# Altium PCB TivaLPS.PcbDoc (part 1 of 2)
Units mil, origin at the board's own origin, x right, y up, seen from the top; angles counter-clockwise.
Board outline 2370 x 2970 mil, 2 copper layers (TopLayer, BottomLayer), stack 30.45 mil thick; 141 components, 125 nets, 734 pads, 136 vias.
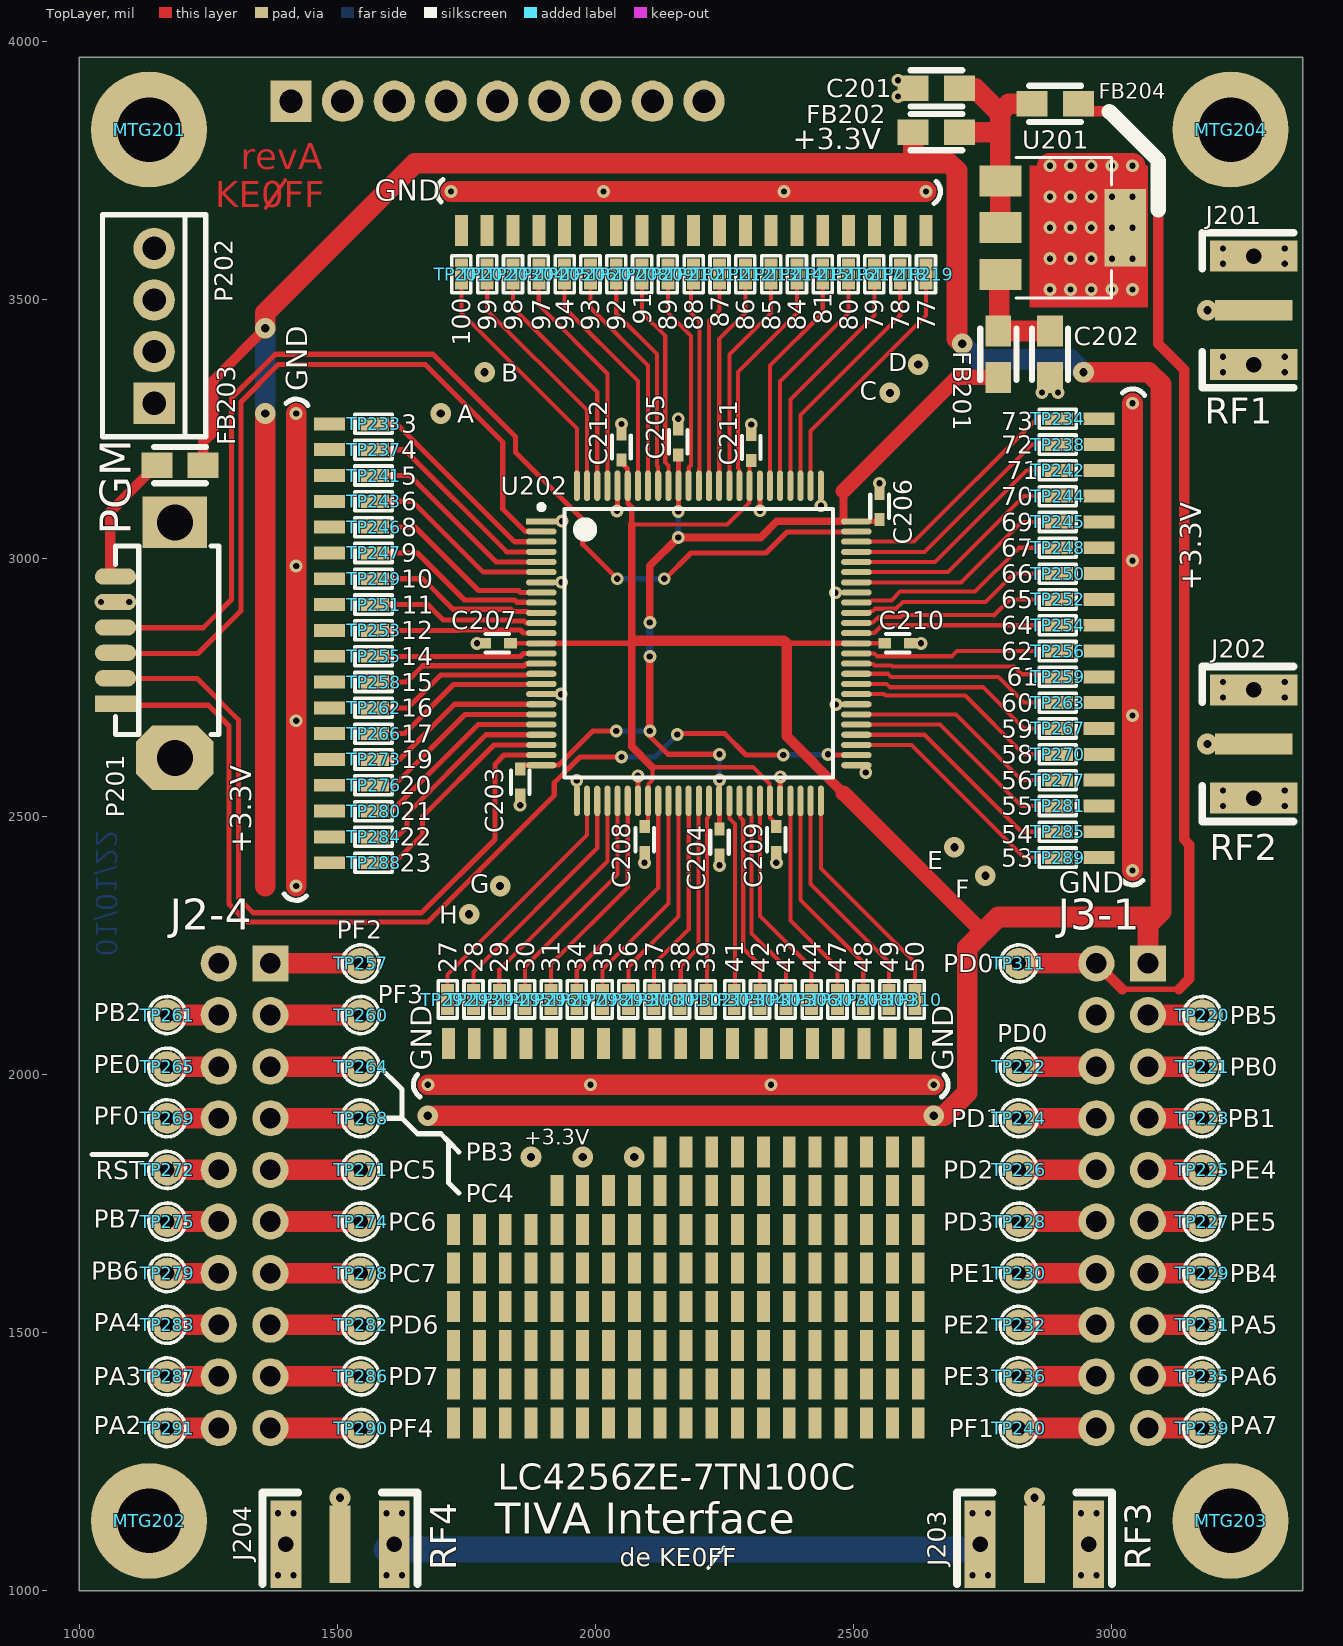
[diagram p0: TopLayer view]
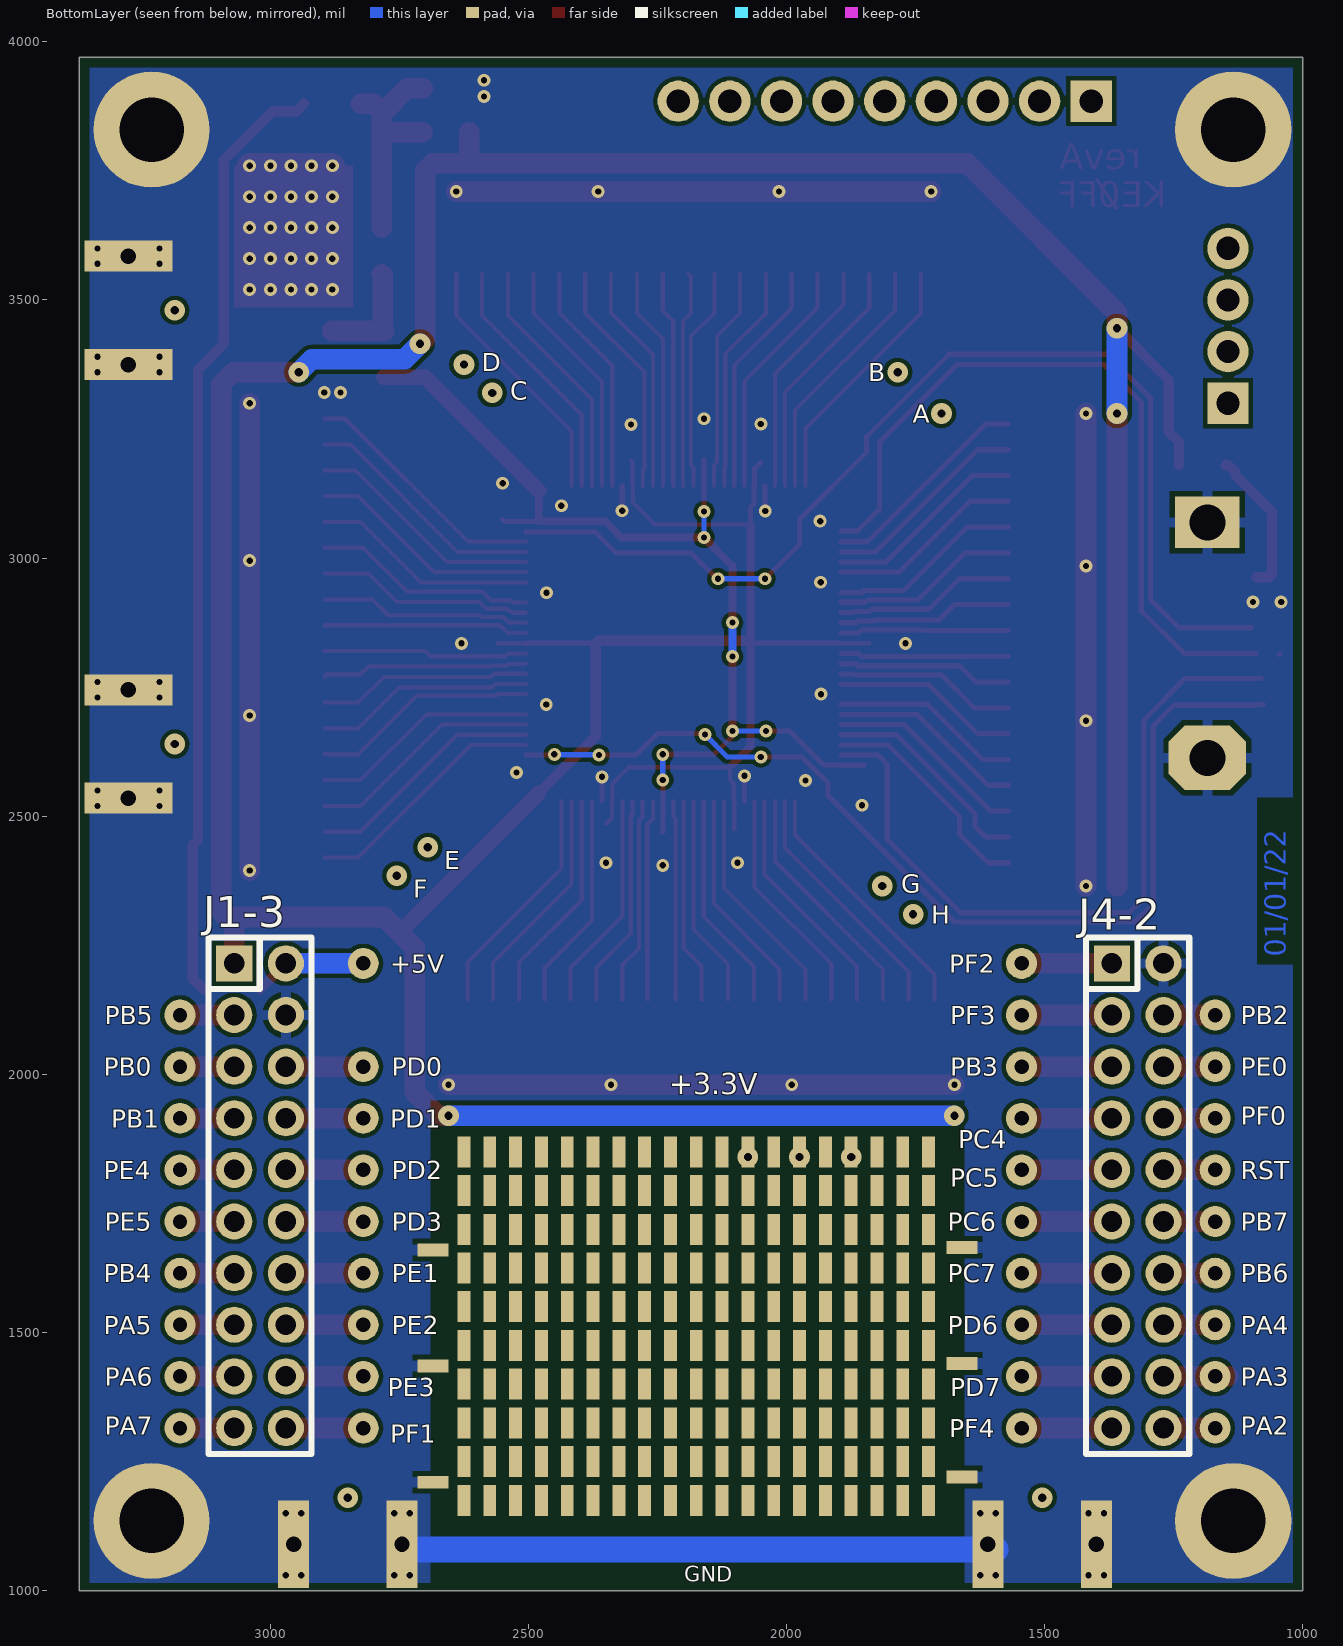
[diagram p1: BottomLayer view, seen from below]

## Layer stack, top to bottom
TopSolder: solder mask 0.4, Solder Resist, Dk 3.5
TopLayer: signal copper 1.4
Dielectric1: dielectric 27.65, FR-4, Dk 4.8
BottomLayer: signal copper 1.4
BottomSolder: solder mask 0.4, Solder Resist, Dk 3.5

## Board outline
1000,1000 3370,1000 3370,3970 1000,3970

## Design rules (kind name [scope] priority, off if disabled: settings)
Clearance Clearance_11 [Component=U202] p1: gap=6 ignorepadtopadclearanceinfootprint=FALSE
Clearance Clearance_8 [HasFootprint('QFP50P900X900X120-49N')] p2: gap=6 ignorepadtopadclearanceinfootprint=FALSE
Clearance Clearance_7 [InNet('FIL_CLK') vs InNet('GND')] p3: gap=6 ignorepadtopadclearanceinfootprint=FALSE
Clearance Clearance_6 [InNet('USB0D_N') vs InNet('USB0D_P')] p4: gap=6 ignorepadtopadclearanceinfootprint=FALSE
Clearance Clearance_10 [InNet('USB1D_N') vs InNet('USB1D_P')] p5: gap=6 ignorepadtopadclearanceinfootprint=FALSE
Clearance Clearance_9 [InNet('USBU_N') vs InNet('USBU_P')] p6: gap=6 ignorepadtopadclearanceinfootprint=FALSE
Clearance Clearance_4 [HasFootprint('0805') vs InNet('GND2')] p7: gap=25 ignorepadtopadclearanceinfootprint=FALSE
Clearance Clearance_3 [InNet('GND2')] p8: gap=8 ignorepadtopadclearanceinfootprint=FALSE
Clearance Clearance_2 [HasFootprint('MT1818')] p9: gap=6 ignorepadtopadclearanceinfootprint=FALSE
Clearance Clearance_1 [HasFootprint('32LFCSP_VQ')] p10: gap=5.7 ignorepadtopadclearanceinfootprint=FALSE
Clearance Clearance_5 [HasFootprint('CON_USB-MICRO')] p11: gap=5.7 ignorepadtopadclearanceinfootprint=FALSE
Clearance [All] p12: gap=8 ignorepadtopadclearanceinfootprint=FALSE
ComponentClearance ComponentClearance_2 [InComponent('TP8') vs InComponent('P2')] p1: gap=0 collisioncheckmode=3 verticalgap=10 showdistances=FALSE
ComponentClearance ComponentClearance_1 [InComponent('C34') vs InComponent('P2')] p2: gap=0 collisioncheckmode=3 verticalgap=10 showdistances=FALSE
ComponentClearance ComponentClearance_6 [InComponent('TP14') vs InComponent('C37')] p3: gap=0 collisioncheckmode=3 verticalgap=10 showdistances=FALSE
ComponentClearance ComponentClearance_9 [InComponent('L3')] p4: gap=0 collisioncheckmode=3 verticalgap=10 showdistances=FALSE
ComponentClearance ComponentClearance_3 [InComponent('D2')] p5: gap=0 collisioncheckmode=3 verticalgap=10 showdistances=FALSE
ComponentClearance ComponentClearance_5 [HasFootprint('0603')] p6: gap=0 collisioncheckmode=3 verticalgap=10 showdistances=FALSE
ComponentClearance ComponentClearance_8 [HasFootprint('TQFP-64')] p7: gap=0 collisioncheckmode=3 verticalgap=10 showdistances=FALSE
ComponentClearance ComponentClearance_10 [HasFootprint('USB_MICRO_SMD')] p8: gap=0 collisioncheckmode=3 verticalgap=10 showdistances=FALSE
ComponentClearance ComponentClearance_7 [HasFootprint('DF782')] p9: gap=0 collisioncheckmode=3 verticalgap=10 showdistances=FALSE
ComponentClearance ComponentClearance_4 [HasFootprint('0402')] p10: gap=0 collisioncheckmode=3 verticalgap=10 showdistances=FALSE
ComponentClearance [All] p11: gap=6 collisioncheckmode=3 verticalgap=10 showdistances=FALSE
DiffPairsRouting [All] p1: maxlimit=10 minlimit=6 mostfreqgap=6 toplayer_minwidth=10 toplayer_maxwidth=30 toplayer_prefwidth=28 bottomlayer_minwidth=10 bottomlayer_maxwidth=30 bottomlayer_prefwidth=28 maxuncoupledlength=500
FabricationTestPointUsage TestPointUsage [All] p1: valid=0 allowmultiple=FALSE
FabricationTestpoint Testpoint [All] p1: side=3 testpointundercomponent=TRUE minsize=40 maxsize=100 preferedsize=60 minholesize=20 maxholesize=40 preferedholesize=32 testpointgrid=1 allowsidetop=TRUE allowsidebottom=TRUE usegrid=TRUE gridtolerance=0.01
HoleSize [All] p1: absolutevalues=TRUE maxlimit=200 minlimit=1 maxpercent=80.000 minpercent=20.000
MinimumAnnularRing [All] p1: minimumring=6
MinimumSolderMaskSliver [All] p1: minsoldermaskwidth=6
PolygonConnect PolygonConnect_1 [(HoleSize    = 12.00) And (ViaDiameter = 25.00)] p1: connectstyle=Direct reliefconductorwidth=10 reliefentries=4 polygonreliefangle="90 Angle" airgapwidth=10
PolygonConnect PolygonConnect_8 [(PadXSize_BottomLayer = 25.00) And (PadYSize_BottomLayer = 20.00)] p2: connectstyle=Relief reliefconductorwidth=10 reliefentries=4 polygonreliefangle="90 Angle" airgapwidth=10
PolygonConnect PolygonConnect_7 [(PadXSize_BottomLayer = 20.00) And (PadYSize_BottomLayer = 25.00)] p3: connectstyle=Relief reliefconductorwidth=10 reliefentries=4 polygonreliefangle="90 Angle" airgapwidth=10
PolygonConnect PolygonConnect_5 [(PadXSize_TopLayer = 60.00) And (PadYSize_TopLayer = 170.00)] p4: connectstyle=Relief reliefconductorwidth=15 reliefentries=4 polygonreliefangle="90 Angle" airgapwidth=10
PolygonConnect PolygonConnect_6 [(PadXSize_TopLayer = 225.00) And (PadYSize_TopLayer = 225.00)] p5: connectstyle=Direct reliefconductorwidth=10 reliefentries=4 polygonreliefangle="90 Angle" airgapwidth=10
PolygonConnect PolygonConnect_4 [(PadXSize_TopLayer = 170.00) And (PadYSize_TopLayer = 60.00)] p6: connectstyle=Direct reliefconductorwidth=10 reliefentries=4 polygonreliefangle="90 Angle" airgapwidth=10
PolygonConnect PolygonConnect_3 [(PadXSize_TopLayer = 200.00) And (PadYSize_TopLayer = 200.00)] p7: connectstyle=Direct reliefconductorwidth=10 reliefentries=4 polygonreliefangle="90 Angle" airgapwidth=10
PolygonConnect PolygonConnect_2 [(PadXSize_TopLayer = 75.00) And (PadYSize_TopLayer = 115.00)] p8: connectstyle=Direct reliefconductorwidth=10 reliefentries=4 polygonreliefangle="90 Angle" airgapwidth=10
PolygonConnect [All] p9: connectstyle=Relief reliefconductorwidth=20 reliefentries=4 polygonreliefangle="90 Angle" airgapwidth=10
RoomDefinition MachShield [InComponentClass('MachShield')] p1: confinementstyle=ConfineOut formatcopy=TRUE lockcomponents=FALSE outline 55,55 730,55 730,190 55,190
RoutingVias [All] p1: holewidth=12 width=25 viastyle="Through Hole" minholewidth=12 minwidth=25 maxholewidth=125 maxwidth=150
ShortCircuit ShortCircuit_1 [InNet('No Net')] p1: allowed=TRUE
ShortCircuit [All] p2: allowed=FALSE
SolderMaskExpansion [All] p1: expansion=4 istentingtop=FALSE
Width [All] p1: maxlimit=150 minlimit=2 preferedwidth=7
23 further rules are at their usual default settings.

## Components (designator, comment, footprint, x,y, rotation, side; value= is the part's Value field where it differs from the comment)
C201 "10uF" 0805 2705,3910 r180 top
C202 "1uF" 0805 2880,3440 r270 top
C203 "0.1uF" 0402 1853.86,2591.37 r270 top
C204 "0.1uF" 0402 2240,2475 r270 top
C205 "0.1uF" 0402 2160,3200 r90 top
C206 "0.1uF" 0402 2550,3075 r90 top
C207 "0.1uF" 0402 1835,2835 r180 top
C208 "0.1uF" 0402 2095,2480 r270 top
C209 "0.1uF" 0402 2350,2480 r270 top
C210 "0.1uF" 0402 2560,2835 r0 top
C211 "0.1uF" 0402 2301.55,3189.04 r90 top
C212 "0.1uF" 0402 2050,3190 r90 top
FB201 "220ohm" 0805 2780,3440 r270 top
FB202 "220ohm" 0805 2615,3825 r0 top
FB203 "220ohm" 0805 1150,3180 r0 top
FB204 "220ohm" 0805 2935,3880 r180 top
J1-3 "TIVA-A" 2X10_PADS 3070,2215 r270 bottom
J4-2 "TIVA-B" 2X10_PADS 1370,2215 r270 bottom (schematic designator J2-4)
J201 "RF1" CONN_SMA_EDGE_062 3275,3480 r180 top
J202 "RF2" CONN_SMA_EDGE_062 3275,2640 r180 top
J203 "RF3" CONN_SMA_EDGE_062_installed 2850,1090 r90 top
J204 "RF4" CONN_SMA_EDGE_062_installed 1505,1090 r90 top
MTG201 "MTG" MTG_125 1135,3830 r90 top
MTG202 "MTG" MTG_125 1135,1135 r90 top
MTG203 "MTG" MTG_125 3230,1135 r90 top
MTG204 "MTG" MTG_125 3230,3830 r90 top
P201 "PGM" CON_1.25MM_6P 1070,2718.15 r90 top
P202 "spare" MOLEX-04 1145,3300 r90 top
TP201 "100" TP 1740,3550 r90 top
TP202 "99" TP 1790,3550 r90 top
TP203 "98" TP 1840,3550 r90 top
TP204 "97" TP 1890,3550 r90 top
TP205 "94" TP 1940,3550 r90 top
TP206 "93" TP 1990,3550 r90 top
TP207 "92" TP 2040,3550 r90 top
TP208 "91" TP 2090,3550 r90 top
TP209 "89" TP 2140,3550 r90 top
TP210 "88" TP 2190,3550 r90 top
TP211 "87" TP 2240,3550 r90 top
TP212 "86" TP 2290,3550 r90 top
TP213 "85" TP 2340,3550 r90 top
TP214 "84" TP 2390,3550 r90 top
TP215 "81" TP 2440,3550 r90 top
TP216 "80" TP 2490,3550 r90 top
TP217 "79" TP 2540,3550 r90 top
TP218 "78" TP 2590,3550 r90 top
TP219 "77" TP 2640,3550 r90 top
TP220 "PB5" TP-TH 3175,2115 r90 top
TP221 "PB0" TP-TH 3175,2015 r90 top
TP222 "PD0" TP-TH 2820,2015 r90 top
TP223 "PB1" TP-TH 3175,1915 r90 top
TP224 "PD1" TP-TH 2820,1915 r90 top
TP225 "PE4" TP-TH 3175,1815 r90 top
TP226 "PD2" TP-TH 2820,1815 r90 top
TP227 "PE5" TP-TH 3175,1715 r90 top
TP228 "PD3" TP-TH 2820,1715 r90 top
TP229 "PB4" TP-TH 3175,1615 r90 top
TP230 "PE1" TP-TH 2820,1615 r90 top
TP231 "PA5" TP-TH 3175,1515 r90 top
TP232 "PE2" TP-TH 2820,1515 r90 top
TP233 "3" TP 1570,3260 r180 top
TP234 "73" TP 2895,3270 r180 top
TP235 "PA6" TP-TH 3175,1415 r90 top
TP236 "PE3" TP-TH 2820,1415 r90 top
TP237 "4" TP 1570,3210 r180 top
TP238 "72" TP 2895,3220 r180 top
TP239 "PA7" TP-TH 3175,1315 r90 top
TP240 "PF1" TP-TH 2820,1315 r90 top
TP241 "5" TP 1570,3160 r180 top
TP242 "71" TP 2895,3170 r180 top
TP243 "6" TP 1570,3110 r180 top
TP244 "70" TP 2895,3120 r180 top
TP245 "69" TP 2895,3070 r180 top
TP246 "8" TP 1570,3060 r180 top
TP247 "9" TP 1570,3010 r180 top
TP248 "67" TP 2895,3020 r180 top
TP249 "10" TP 1570,2960 r180 top
TP250 "66" TP 2895,2970 r180 top
TP251 "11" TP 1570,2910 r180 top
TP252 "65" TP 2895,2920 r180 top
TP253 "12" TP 1570,2860 r180 top
TP254 "64" TP 2895,2870 r180 top
TP255 "14" TP 1570,2810 r180 top
TP256 "62" TP 2895,2820 r180 top
TP257 "PF2" TP-TH 1545,2215 r90 top
TP258 "15" TP 1570,2760 r180 top
TP259 "61" TP 2895,2770 r180 top
TP260 "PF3" TP-TH 1545,2115 r90 top
TP261 "PB2" TP-TH 1170,2115 r90 top
TP262 "16" TP 1570,2710 r180 top
TP263 "60" TP 2895,2720 r180 top
TP264 "PB3" TP-TH 1545,2015 r90 top
TP265 "PE0" TP-TH 1170,2015 r90 top
TP266 "17" TP 1570,2660 r180 top
TP267 "59" TP 2895,2670 r180 top
TP268 "PC4" TP-TH 1545,1915 r90 top
TP269 "PF0" TP-TH 1170,1915 r90 top
TP270 "58" TP 2895,2620 r180 top
TP271 "PC5" TP-TH 1545,1815 r90 top
TP272 "/RST" TP-TH 1170,1815 r90 top
TP273 "19" TP 1570,2610 r180 top
TP274 "PC6" TP-TH 1545,1715 r90 top
TP275 "PB7" TP-TH 1170,1715 r90 top
TP276 "20" TP 1570,2560 r180 top
TP277 "56" TP 2895,2570 r180 top
TP278 "PC7" TP-TH 1545,1615 r90 top
TP279 "PB6" TP-TH 1170,1615 r90 top
TP280 "21" TP 1570,2510 r180 top
TP281 "55" TP 2895,2520 r180 top
TP282 "PD6" TP-TH 1545,1515 r90 top
TP283 "PA4" TP-TH 1170,1515 r90 top
TP284 "22" TP 1570,2460 r180 top
TP285 "54" TP 2895,2470 r180 top
TP286 "PD7" TP-TH 1545,1415 r90 top
TP287 "PA3" TP-TH 1170,1415 r90 top
TP288 "23" TP 1570,2410 r180 top
TP289 "53" TP 2895,2420 r180 top
TP290 "PF4" TP-TH 1545,1315 r90 top
TP291 "PA2" TP-TH 1170,1315 r90 top
TP292 "27" TP 1713.46,2145.06 r90 top
TP293 "28" TP 1763.46,2145.06 r90 top
TP294 "29" TP 1813.46,2145.06 r90 top
TP295 "30" TP 1863.46,2145.06 r90 top
TP296 "31" TP 1913.46,2145.06 r90 top
TP297 "34" TP 1963.46,2145.06 r90 top
TP298 "35" TP 2013.46,2145.06 r90 top
TP299 "36" TP 2063.46,2145.06 r90 top
TP300 "37" TP 2113.46,2145.06 r90 top
TP301 "38" TP 2163.46,2145.06 r90 top
TP302 "39" TP 2213.46,2145.06 r90 top
TP303 "41" TP 2268.46,2145.06 r90 top
TP304 "42" TP 2318.46,2145.06 r90 top
TP305 "43" TP 2368.46,2145.06 r90 top
TP306 "44" TP 2418.46,2145.06 r90 top
TP307 "47" TP 2468.46,2145.06 r90 top
TP308 "48" TP 2518.46,2145.06 r90 top
TP309 "49" TP 2568.46,2145.06 r270 top
TP310 "50" TP 2618.46,2145.06 r270 top
TP311 "PD0" TP-TH 2820,2215 r90 top
U201 "MC33375ST-1.8T3G" SOT223 2905,3640 r0 top
U202 "LC4256ZE-7TN100C" SQFP50P1600X1600X245-100N 2200,2835 r0 top

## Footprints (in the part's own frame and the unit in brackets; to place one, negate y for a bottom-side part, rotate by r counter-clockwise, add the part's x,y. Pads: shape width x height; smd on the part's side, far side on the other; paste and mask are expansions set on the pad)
2X10_PADS [mil]
  rect 70x70 hole 40: 1(0,0)
  round 70 hole 40: 2(0,100) 3(100,0) 4(100,100) 5(200,0) 6(200,100) 7(300,0) 8(300,100) 9(400,0) 10(400,100) 11(500,0) 12(500,100) 13(600,0) 14(600,100) 15(700,0) 16(700,100) 17(800,0) 18(800,100) 19(900,0) 20(900,100)
  silkscreen extent -50,-50 950,150, body extent -50,-50 950,150, height 441
0402 [mil]
  rect 25x20 smd: 1(0,0) 2(50,0)
  silkscreen extent 3,-18 48,18, body extent 5,-10 45,10, height 10
0805 [mil]
  rect 60x50 smd: 1(0,0) 2(90,0)
  silkscreen extent -5,-35 95,35, body extent -5,-25 95,25, height 25
CON_1.25MM_6P [mil]
  rect 31.5x80 smd: 1(0,0)
  oval 31.5x80 smd: 2(49.21,0) 3(98.43,0) 4(147.64,0) 5(196.85,0) 6(246.06,0)
  oct 125x150 hole 70: 7(-105,-115)
  rect 100x125 hole 70: 8(351,-115)
  silkscreen extent -60,-200 305,0, body extent -117,-174 362,19, height 189
CONN_SMA_EDGE_062 [mil]
  rect 150x40 smd: 1(0,0)
  rect 170x60 hole 30: 2(0,-105) 3(0,105)
  silkscreen extent -77,-150 100,150
CONN_SMA_EDGE_062_installed [mil]
  rect 150x40 smd: 1(0,0)
  rect 170x60 hole 30: 2(0,-105) 3(0,105)
  silkscreen extent -77,-150 100,150, body extent -461,-125 63,125, height 150
MOLEX-04 [mil] "CON, TH, 4POS"
  rect 80x80 hole 45: 1(0,0)
  round 80 hole 45: 2(100,0) 3(200,0) 4(300,0)
  silkscreen extent -65,-100 365,100
MTG_125 [mil] "HOL, MTG, 0.125 IN"
  round 225 hole 125: 1(0,0)
SOT223 [mil]
  rect 81x60 smd mask+2: 1(-121,90.5) 2(-121,0) 3(-121,-90.5)
  rect 81x150 smd mask+2: 4(121,0)
  silkscreen extent -90,-136 94,136, body extent -141,-126 135,130, height 65
SQFP50P1600X1600X245-100N [mm] "SQFP, 100-Leads, Body 14.00x14.00mm, Pitch 0.50mm, IPC Medium Density"
  rect 1.5x0.3 smd mask+0.05: 1(-7.75,6)
  oval 1.5x0.3 smd mask+0.05: 2(-7.75,5.5) 3(-7.75,5) 4(-7.75,4.5) 5(-7.75,4) 6(-7.75,3.5) 7(-7.75,3) 8(-7.75,2.5) 9(-7.75,2) 10(-7.75,1.5) 11(-7.75,1) 12(-7.75,0.5) 13(-7.75,0) 14(-7.75,-0.5) 15(-7.75,-1) 16(-7.75,-1.5) 17(-7.75,-2) 18(-7.75,-2.5) 19(-7.75,-3) 20(-7.75,-3.5) 21(-7.75,-4) 22(-7.75,-4.5) 23(-7.75,-5) 24(-7.75,-5.5) 25(-7.75,-6) 51(7.75,-6) 52(7.75,-5.5) 53(7.75,-5) 54(7.75,-4.5) 55(7.75,-4) 56(7.75,-3.5) 57(7.75,-3) 58(7.75,-2.5) 59(7.75,-2) 60(7.75,-1.5) 61(7.75,-1) 62(7.75,-0.5) 63(7.75,0) 64(7.75,0.5) 65(7.75,1) 66(7.75,1.5) 67(7.75,2) 68(7.75,2.5) 69(7.75,3) 70(7.75,3.5) 71(7.75,4) 72(7.75,4.5) 73(7.75,5) 74(7.75,5.5) 75(7.75,6)
  oval 0.3x1.5 smd mask+0.05: 26(-6,-7.75) 27(-5.5,-7.75) 28(-5,-7.75) 29(-4.5,-7.75) 30(-4,-7.75) 31(-3.5,-7.75) 32(-3,-7.75) 33(-2.5,-7.75) 34(-2,-7.75) 35(-1.5,-7.75) 36(-1,-7.75) 37(-0.5,-7.75) 38(0,-7.75) 39(0.5,-7.75) 40(1,-7.75) 41(1.5,-7.75) 42(2,-7.75) 43(2.5,-7.75) 44(3,-7.75) 45(3.5,-7.75) 46(4,-7.75) 47(4.5,-7.75) 48(5,-7.75) 49(5.5,-7.75) 50(6,-7.75) 76(6,7.75) 77(5.5,7.75) 78(5,7.75) 79(4.5,7.75) 80(4,7.75) 81(3.5,7.75) 82(3,7.75) 83(2.5,7.75) 84(2,7.75) 85(1.5,7.75) 86(1,7.75) 87(0.5,7.75) 88(0,7.75) 89(-0.5,7.75) 90(-1,7.75) 91(-1.5,7.75) 92(-2,7.75) 93(-2.5,7.75) 94(-3,7.75) 95(-3.5,7.75) 96(-4,7.75) 97(-4.5,7.75) 98(-5,7.75) 99(-5.5,7.75) 100(-6,7.75)
  silkscreen extent -7.87,-6.6 6.6,6.82, body extent -8,-8 8,8, height 2.45
TP [mil]
  rect 60x25 smd mask+2: 1(0,0)
  silkscreen extent -36,-18 36,18
TP-TH [mil]
  round 60 hole 28 mask+2: 1(0,0)
  silkscreen extent -36,-36 36,36

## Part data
C201 C202 C203 C204 C205 C206 C207 C208 C209 C210 C211 C212: library part "CAP 0805"
FB201 FB202 FB203 FB204: library part FB, "BD, FRITE, SMD"
J1-3 J4-2: library part "CON, TH, 2x10"
J201 J202 J203 J204: library part CON_3P, "CON, SIP, 3 POS"
P201: library part HEADER-6-PIN-RT-ANG, "6-PIN JTAG HDR"
P202: library part CON_4P, "CON, DIP, 16 POS"
TP201 TP202 TP203 TP204 TP205 TP206 TP207 TP208 TP209 TP210 TP211 TP212 TP213 TP214 TP215 TP216 TP217 TP218 TP219 TP220 TP221 TP222 TP223 TP224 TP225 TP226 TP227 TP228 TP229 TP230 TP231 TP232 TP233 TP234 TP235 TP236 TP237 TP238 TP239 TP240 TP241 TP242 TP243 TP244 TP245 TP246 TP247 TP248 TP249 TP250 TP251 TP252 TP253 TP254 TP255 TP256 TP257 TP258 TP259 TP260 TP261 TP262 TP263 TP264 TP265 TP266 TP267 TP268 TP269 TP270 TP271 TP272 TP273 TP274 TP275 TP276 TP277 TP278 TP279 TP280 TP281 TP282 TP283 TP284 TP285 TP286 TP287 TP288 TP289 TP290 TP291 TP292 TP293 TP294 TP295 TP296 TP297 TP298 TP299 TP300 TP301 TP302 TP303 TP304 TP305 TP306 TP307 TP308 TP309 TP310 TP311: library part TP
U201: library part MC33375ST-3.3T3G

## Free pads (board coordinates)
  rect 80x80 hole 45: 1(1410,3885)
  round 80 hole 45: 2(1510,3885) 3(1610,3885) 4(1710,3885) 5(1810,3885) 6(1910,3885) 7(2010,3885) 8(2110,3885) 9(2210,3885)
  rect 60x25 smd mask+2: 169(1485,2410) 169(1485,2460) 169(1485,2510) 169(1485,2560) 169(1485,2610) 169(1485,2660) 169(1485,2710) 169(1485,2760) 169(1485,2810) 169(1485,2860) 169(1485,2910) 169(1485,2960) 169(1485,3010) 169(1485,3060) 169(1485,3110) 169(1485,3160) 169(1485,3210) 169(1485,3260) 169(2975,2420) 169(2975,2470) 169(2975,2520) 169(2975,2570) 169(2975,2620) 169(2975,2670) 169(2975,2720) 169(2975,2770) 169(2975,2820) 169(2975,2870) 169(2975,2920) 169(2975,2970) 169(2975,3020) 169(2975,3070) 169(2975,3120) 169(2975,3170) 169(2975,3220) 169(2975,3270)
  rect 60x25 smd far side mask+2: 169(1660,1220) 169(1660,1440) 169(1660,1665) 169(2685,1210) 169(2685,1435) 169(2685,1660)
  rect 25x60 smd mask+2: 169(1715,2060) 169(1725,1325) 169(1725,1400) 169(1725,1475) 169(1725,1550) 169(1725,1625) 169(1725,1700) 169(1740,3635) 169(1765,2060) 169(1775,1325) 169(1775,1400) 169(1775,1475) 169(1775,1550) 169(1775,1625) 169(1775,1700) 169(1790,3635) 169(1815,2060) 169(1825,1325) 169(1825,1400) 169(1825,1475) 169(1825,1550) 169(1825,1625) 169(1825,1700) 169(1840,3635) 169(1865,2060) 169(1875,1325) 169(1875,1400) 169(1875,1475) 169(1875,1550) 169(1875,1625) 169(1875,1700) 169(1890,3635) 169(1915,2060) 169(1925,1325) 169(1925,1400) 169(1925,1475) 169(1925,1550) 169(1925,1625) 169(1925,1700) 169(1925,1775) 169(1940,3635) 169(1965,2060) 169(1975,1325) 169(1975,1400) 169(1975,1475) 169(1975,1550) 169(1975,1625) 169(1975,1700) 169(1975,1775) 169(1990,3635) 169(2015,2060) 169(2025,1325) 169(2025,1400) 169(2025,1475) 169(2025,1550) 169(2025,1625) 169(2025,1700) 169(2025,1775) 169(2040,3635) 169(2065,2060) 169(2075,1325) 169(2075,1400) 169(2075,1475) 169(2075,1550) 169(2075,1625) 169(2075,1700) 169(2075,1775) 169(2090,3635) 169(2115,2060) 169(2125,1325) 169(2125,1400) 169(2125,1475) 169(2125,1550) 169(2125,1625) 169(2125,1700) 169(2125,1775) 169(2125,1850) 169(2140,3635) 169(2165,2060) 169(2175,1325) 169(2175,1400) 169(2175,1475) 169(2175,1550) 169(2175,1625) 169(2175,1700) 169(2175,1775) 169(2175,1850) 169(2190,3635) 169(2215,2060) 169(2225,1325) 169(2225,1400) 169(2225,1475) 169(2225,1550) 169(2225,1625) 169(2225,1700) 169(2225,1775) 169(2225,1850) 169(2240,3635) 169(2265,2060) 169(2275,1325) 169(2275,1400) 169(2275,1475) 169(2275,1550) 169(2275,1625) 169(2275,1700) 169(2275,1775) 169(2275,1850) 169(2290,3635) 169(2320,2060) 169(2325,1325) 169(2325,1400) 169(2325,1475) 169(2325,1550) 169(2325,1625) 169(2325,1700) 169(2325,1775) 169(2325,1850) 169(2340,3635) 169(2370,2060) 169(2375,1325) 169(2375,1400) 169(2375,1475) 169(2375,1550) 169(2375,1625) 169(2375,1700) 169(2375,1775) 169(2375,1850) 169(2390,3635) 169(2420,2060) 169(2425,1325) 169(2425,1400) 169(2425,1475) 169(2425,1550) 169(2425,1625) 169(2425,1700) 169(2425,1775) 169(2425,1850) 169(2440,3635) 169(2470,2060) 169(2475,1325) 169(2475,1400) 169(2475,1475) 169(2475,1550) 169(2475,1625) 169(2475,1700) 169(2475,1775) 169(2475,1850) 169(2490,3635) 169(2520,2060) 169(2525,1325) 169(2525,1400) 169(2525,1475) 169(2525,1550) 169(2525,1625) 169(2525,1700) 169(2525,1775) 169(2525,1850) 169(2540,3635) 169(2570,2060) 169(2575,1325) 169(2575,1400) 169(2575,1475) 169(2575,1550) 169(2575,1625) 169(2575,1700) 169(2575,1775) 169(2575,1850) 169(2590,3635) 169(2620,2060) 169(2625,1325) 169(2625,1400) 169(2625,1475) 169(2625,1550) 169(2625,1625) 169(2625,1700) 169(2625,1775) 169(2625,1850) 169(2640,3635)
  rect 25x60 smd far side mask+2: 169(1725,1175) 169(1725,1250) 169(1725,1325) 169(1725,1400) 169(1725,1475) 169(1725,1550) 169(1725,1625) 169(1725,1700) 169(1725,1775) 169(1725,1850) 169(1775,1175) 169(1775,1250) 169(1775,1325) 169(1775,1400) 169(1775,1475) 169(1775,1550) 169(1775,1625) 169(1775,1700) 169(1775,1775) 169(1775,1850) 169(1825,1175) 169(1825,1250) 169(1825,1325) 169(1825,1400) 169(1825,1475) 169(1825,1550) 169(1825,1625) 169(1825,1700) 169(1825,1775) 169(1825,1850) 169(1875,1175) 169(1875,1250) 169(1875,1325) 169(1875,1400) 169(1875,1475) 169(1875,1550) 169(1875,1625) 169(1875,1700) 169(1875,1775) 169(1875,1850) 169(1925,1175) 169(1925,1250) 169(1925,1325) 169(1925,1400) 169(1925,1475) 169(1925,1550) 169(1925,1625) 169(1925,1700) 169(1925,1775) 169(1925,1850) 169(1975,1175) 169(1975,1250) 169(1975,1325) 169(1975,1400) 169(1975,1475) 169(1975,1550) 169(1975,1625) 169(1975,1700) 169(1975,1775) 169(1975,1850) 169(2025,1175) 169(2025,1250) 169(2025,1325) 169(2025,1400) 169(2025,1475) 169(2025,1550) 169(2025,1625) 169(2025,1700) 169(2025,1775) 169(2025,1850) 169(2075,1175) 169(2075,1250) 169(2075,1325) 169(2075,1400) 169(2075,1475) 169(2075,1550) 169(2075,1625) 169(2075,1700) 169(2075,1775) 169(2075,1850) 169(2125,1175) 169(2125,1250) 169(2125,1325) 169(2125,1400) 169(2125,1475) 169(2125,1550) 169(2125,1625) 169(2125,1700) 169(2125,1775) 169(2125,1850) 169(2175,1175) 169(2175,1250) 169(2175,1325) 169(2175,1400) 169(2175,1475) 169(2175,1550) 169(2175,1625) 169(2175,1700) 169(2175,1775) 169(2175,1850) 169(2225,1175) 169(2225,1250) 169(2225,1325) 169(2225,1400) 169(2225,1475) 169(2225,1550) 169(2225,1625) 169(2225,1700) 169(2225,1775) 169(2225,1850) 169(2275,1175) 169(2275,1250) 169(2275,1325) 169(2275,1400) 169(2275,1475) 169(2275,1550) 169(2275,1625) 169(2275,1700) 169(2275,1775) 169(2275,1850) 169(2325,1175) 169(2325,1250) 169(2325,1325) 169(2325,1400) 169(2325,1475) 169(2325,1550) 169(2325,1625) 169(2325,1700) 169(2325,1775) 169(2325,1850) 169(2375,1175) 169(2375,1250) 169(2375,1325) 169(2375,1400) 169(2375,1475) 169(2375,1550) 169(2375,1625) 169(2375,1700) 169(2375,1775) 169(2375,1850) 169(2425,1175) 169(2425,1250) 169(2425,1325) 169(2425,1400) 169(2425,1475) 169(2425,1550) 169(2425,1625) 169(2425,1700) 169(2425,1775) 169(2425,1850) 169(2475,1175) 169(2475,1250) 169(2475,1325) 169(2475,1400) 169(2475,1475) 169(2475,1550) 169(2475,1625) 169(2475,1700) 169(2475,1775) 169(2475,1850) 169(2525,1175) 169(2525,1250) 169(2525,1325) 169(2525,1400) 169(2525,1475) 169(2525,1550) 169(2525,1625) 169(2525,1700) 169(2525,1775) 169(2525,1850) 169(2575,1175) 169(2575,1250) 169(2575,1325) 169(2575,1400) 169(2575,1475) 169(2575,1550) 169(2575,1625) 169(2575,1700) 169(2575,1775) 169(2575,1850) 169(2625,1175) 169(2625,1250) 169(2625,1325) 169(2625,1400) 169(2625,1475) 169(2625,1550) 169(2625,1625) 169(2625,1700) 169(2625,1775) 169(2625,1850)

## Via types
v1: diameter 25, hole 12, TopLayer to BottomLayer, 115 vias
v2: diameter 40, hole 16, TopLayer to BottomLayer, 19 vias
v3: diameter 40, hole 16, TopLayer to BottomLayer, tented top, 2 vias

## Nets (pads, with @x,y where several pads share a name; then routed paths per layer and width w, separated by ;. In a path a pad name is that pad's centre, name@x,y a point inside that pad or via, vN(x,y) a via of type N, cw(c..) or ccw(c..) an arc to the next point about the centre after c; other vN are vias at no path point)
+1.8V: C202.1 FB201.1 U201.3 | length 211.2
  TopLayer w40: U201.3@2784,3549.5 2782,3547.5 2782,3442 FB201.1@2780,3440 C202.1@2880,3440
+3.3Vm: C207.1 C208.1 C209.1 C210.1 C211.1 C212.1 FB202.1 FB203.2 J1-3.1 U202.13 U202.33 U202.45 U202.63 U202.83 U202.95 | length 10592
  TopLayer w8: C207.1@1840,2835 U202.13@1894.88,2835 ; U202.95@2062.2,3140.12 U202.95@2062.93,3139.39 ; 2070,3065 2255,3065 2297.7,3107.7 2297.7,3139.39 U202.83@2298.43,3140.12 2298.43,3185.92 C211.1@2301.55,3189.04 ; C208.1@2101.57,2474.07 U202.33@2101.57,2529.88 2102.3,2530.61 2102.3,2562.3 2110,2570 2110,2595 2305,2595 2337.07,2562.93 2337.07,2530.61 U202.45@2337.8,2529.88 2337.93,2529.75 2337.93,2497.07 C209.1@2350,2485 ; U202.63@2505.12,2835 C210.1@2560,2835
  TopLayer w10: U202.13@1894.88,2835 2070,2835 ; C212.1@2050,3185 2061.95,3173.05 2061.95,3140.37 U202.95@2062.2,3140.12 ; U202.95@2062.93,3139.39 2062.93,3105.71 2070,3098.65 2070,3065 ; 2370,2835 U202.63@2505.12,2835
  TopLayer w15: 2070,3065 2070,2835 2070,2635 2110,2595
  TopLayer w20: FB203.2@1240,3180 1240,3225 1260,3245 1260,3345 v2(1360,3445) ; 1355,3180 1355,2970 1360,2965 ; 2070,2835 2075,2840 2365,2840 2370,2835 2370,2655 2480,2545
  TopLayer w30: 2480,2545 2750,2275
  TopLayer w40: 1360,2365 1360,2965 v2(1360,3280) ; v2(1360,3445) 1360,3475 1650,3765 1720,3765 2615,3765 ; v2(1675,1920) v2(2655,1920) 2675,1920 2720,1965 2720,2245 2742.25,2267.25 ; FB202.1@2615,3825 2615,3765 ; v3(2710,3415) 2700,3425 2700,3750 2685,3765 2615,3765 ; 2750,2275 2780,2305 3070,2305 3085,2305 ; v3(2945,3360) 3071.57,3360 3095,3336.57 3095,2315 3085,2305 ; J1-3.1@3070,2215 3070,2290 3085,2305
  BottomLayer w40: v2(1360,3280) v2(1360,3445) ; v2(1675,1920) v2(2655,1920) ; v3(2710,3415) 2740,3385 2920,3385 v3(2945,3360)
+5Vm: FB204.1 J1-3.2 TP311.1 | length 2319.9
  TopLayer w10: 3020,2165 3130,2165
  TopLayer w20: FB204.1@2935,3880 2949.19,3865.81 2995,3865.81 3090,3770.81 3090,3415 3140,3365 3140,2455 3150,2445 3150,2185 3130,2165 ; J1-3.2@2970,2215 3020,2165
  TopLayer w40: TP311.1@2820,2215 J1-3.2@2970,2215
  BottomLayer w40: TP311.1@2820,2215 J1-3.2@2970,2215
/RSTm: J4-2.10 TP272.1 | length 100
  TopLayer w40: TP272.1@1170,1815 J4-2.10@1270,1815
GNDm: C201.2 C202.2 C203.2 C204.2 C205.2 C206.2 C207.2 C208.2 C209.2 C210.2 C211.2 C212.2 J1-3.4 J4-2.2 J201.2 J201.3 J202.2 J202.3 J203.2 J203.3 J204.2 J204.3 MTG201.1 MTG202.1 MTG203.1 MTG204.1 P201.5 P201.7 P201.8 pad.169@1660,1220 pad.169@1660,1440 pad.169@1660,1665 pad.169@2685,1210 pad.169@2685,1435 pad.169@2685,1660 U201.4 U202.1 U202.7 U202.18 U202.26 U202.32 U202.46 U202.51 U202.57 U202.68 U202.76 U202.82 U202.96 | length 5232.3
  TopLayer w6: MTG203.1@3230,1135 MTG203.1@3235,1130
  TopLayer w10: v1(2041.36,3090.99) 2042.35,3091.98 2042.35,3139.95 U202.96@2042.52,3140.12 ; v1(2081.79,2578.29) 2081.84,2578.24 2081.84,2529.93 U202.32@2081.89,2529.88 ; U202.82@2318.11,3140.12 2318.31,3139.91 2318.31,3092.02 v1(2318.52,3091.82) ; U202.46@2357.48,2529.88 2357.63,2530.03 2357.63,2576.22 v1(2357.78,2576.38)
  TopLayer w40: v1(1420,2365) v1(1420,2685) v1(1420,2985) v1(1420,3280) ; v1(1675,1980) v1(1990,1980) v1(2340,1980) v1(2655,1980) ; v1(1720,3710) v1(2015,3710) v1(2365,3710) v1(2640,3710) ; v1(3040,2395) v1(3040,2695) v1(3040,2995) v1(3040,3300)
  TopLayer w50: v1(2880,3760) v1(2920,3760) v1(2960,3760) v1(3000,3760) v1(3040,3760)
  BottomLayer w6: MTG203.1@3230,1135 MTG203.1@3235,1130
  BottomLayer w50: J204.2@1595,1080 J203.3@2740,1080
  other v1: 1385,1030 1415,1030 1595,1030 1625,1030 2730,1030 2760,1030 2940,1030 2970,1030 1385,1150 1415,1150 1595,1150 1625,1150 2730,1150 2760,1150 2940,1150 2970,1150 2240,2405 2095,2410 2350,2410 3215,2520 3335,2520 1853.86,2521.37 3215,2550 3335,2550 1963.44,2569.44 2523.18,2584.6 2465.55,2716.46 3215,2730 3335,2730 1933.15,2736.5 3215,2760 3335,2760 1770,2835 2630,2835 1042.05,2915 1096.65,2915 2464.85,2932.91 1934.08,2953.19 1935.01,3071.55 2436.42,3101.37 2550,3145 2301.55,3259.04 2050,3260 2160,3270 2864.39,3320.96 2895.61,3320.96 3215,3360 3335,3360 3215,3390 3335,3390 2880,3520 2920,3520 2960,3520 3000,3520 3040,3520 3215,3570 3335,3570 2880,3580 2920,3580 2960,3580 3000,3580 3040,3580 3215,3600 3335,3600 2880,3640 2920,3640 2960,3640 3000,3640 3040,3640 2880,3700 2920,3700 2960,3700 3000,3700 3040,3700 2585.96,3894.39 2585.96,3925.61
NetC201_1: C201.1 FB202.2 FB204.2 U201.1 U201.2 | length 437.2
  TopLayer w40: FB202.2@2705,3825 2784,3825 ; C201.1@2705,3910 2735,3910 2775,3870 ; U201.2@2784,3640 2784,3825 ; FB204.2@2825,3880 2800,3880 2784,3864 2784,3825
NetFB203_1: FB203.1 P201.6 | length 284.5
  TopLayer w20: P201.6@1090,2962.64 1065.31,2962.64 1060,2967.95 1060,3090 1130,3160 1130,3165 1145,3180 FB203.1@1150,3180
NetTP201_1: TP201.1 U202.100 | length 502.6
  TopLayer w8: TP201.1@1740,3550 1740,3475 1963.78,3251.22 U202.100@1963.78,3140.12
NetTP202_1: TP202.1 U202.99 | length 490
  TopLayer w8: TP202.1@1790,3550 1790,3480 1983.46,3286.54 U202.99@1983.46,3140.12
NetTP203_1: TP203.1 U202.98 | length 477.5
  TopLayer w8: TP203.1@1840,3550 1840,3485 2003.15,3321.85 U202.98@2003.15,3140.12
NetTP204_1: TP204.1 U202.97 | length 464.9
  TopLayer w8: TP204.1@1890,3550 1890,3490 2022.83,3357.17 U202.97@2022.83,3140.12
NetTP205_1: TP205.1 U202.94 | length 468.7
  TopLayer w8: TP205.1@1940,3550 1940,3485 2081.89,3343.11 U202.94@2081.89,3140.12
NetTP206_1: TP206.1 U202.93 | length 456.1
  TopLayer w8: TP206.1@1990,3550 1990,3485 2101.57,3373.43 U202.93@2101.57,3140.12
NetTP207_1: TP207.1 U202.92 | length 443.5
  TopLayer w8: TP207.1@2040,3550 2040,3474 2119,3395 2119,3178.37 2120.53,3176.84 2120.53,3140.85 U202.92@2121.26,3140.12
NetTP208_1: TP208.1 U202.91 | length 431
  TopLayer w8: TP208.1@2090,3550 2090,3475 2135,3430 2135,3185 2140.94,3179.06 U202.91@2140.94,3140.12
NetTP209_1: TP209.1 U202.89 | length 430.5
  TopLayer w8: TP209.1@2140,3550 2140,3475 2185,3430 2185,3180 2180.32,3175.32 U202.89@2180.32,3140.12
NetTP210_1: TP210.1 U202.88 | length 419
  TopLayer w8: TP210.1@2190,3550 2185,3545 2185,3475 2201,3459 2201,3173.37 2200.73,3173.1 2200.73,3140.85 U202.88@2200,3140.12
NetTP211_1: TP211.1 U202.87 | length 418.3
  TopLayer w8: U202.87@2219.68,3140.12 2219.68,3459.69 2240,3480 TP211.1@2240,3550
NetTP212_1: TP212.1 U202.86 | length 430.9
  TopLayer w8: U202.86@2239.37,3140.12 2239.37,3424.37 2290,3475 TP212.1@2290,3550
NetTP213_1: TP213.1 U202.85 | length 443.4
  TopLayer w8: U202.85@2259.06,3140.12 2259.06,3394.06 2340,3475 TP213.1@2340,3550
NetTP214_1: TP214.1 U202.84 | length 458.7
  TopLayer w8: U202.84@2278.74,3140.12 2278.01,3140.85 2278.01,3171.99 2275.5,3174.5 2275.5,3360.5 2390,3475 TP214.1@2390,3550
NetTP215_1: TP215.1 U202.81 | length 452.2
  TopLayer w8: U202.81@2337.8,3140.12 2337.8,3372.8 2440,3475 TP215.1@2440,3550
